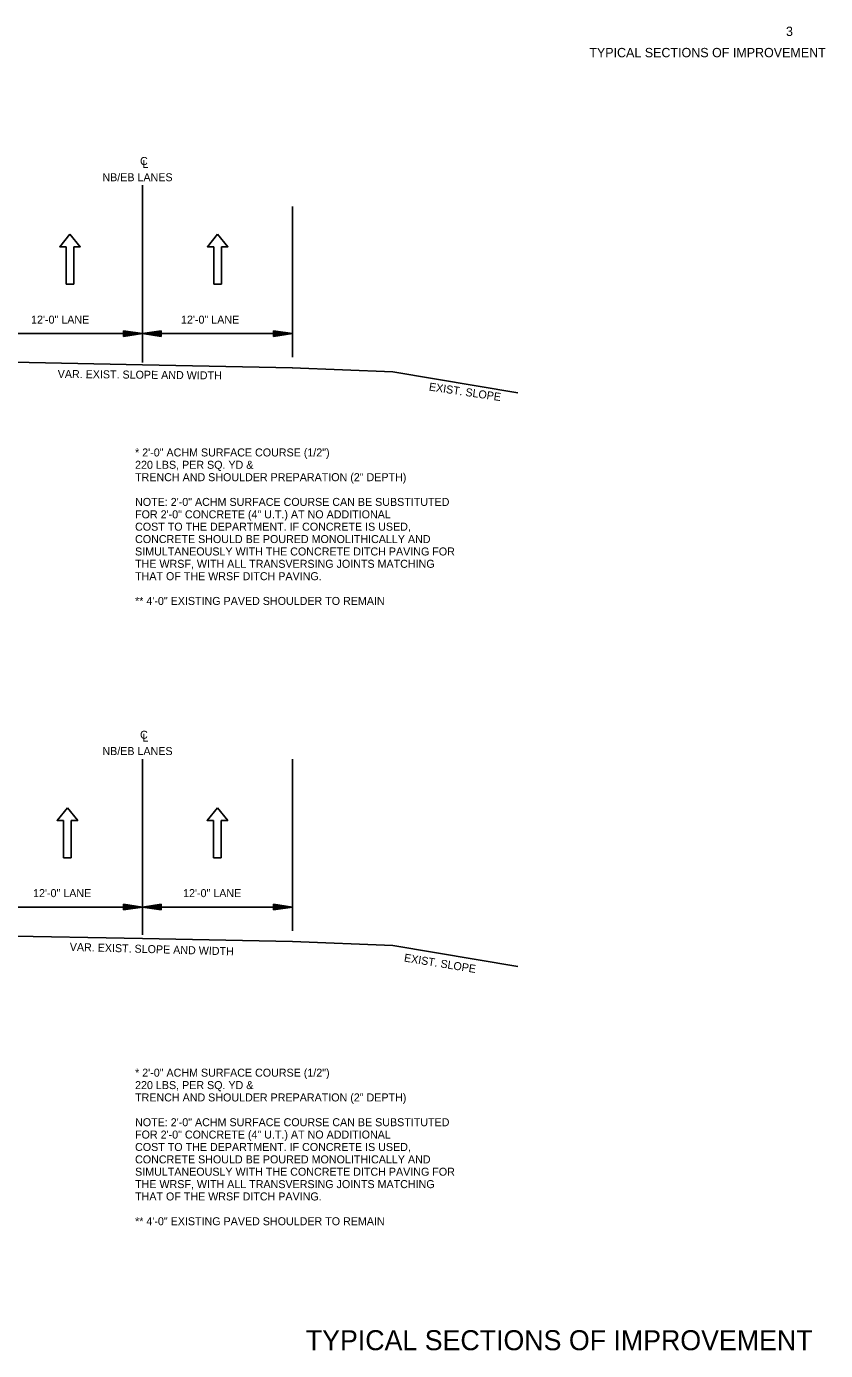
# Model space of a CAD drawing. Extents: x 1641422 to 1649187, y 577497 to 580642.
# Drawn here: x 1646438 to 1647636, y 578610 to 580596 of the extents above; entities that cross this region are included whole.
import ezdxf

# ---------------------------------------------------------------- set-up
doc = ezdxf.new("R2010")
doc.units = 0
doc.layers.add('R_Border', color=7, linetype='Continuous')
doc.layers.add('R_Draft', color=7, linetype='Continuous')

msp = doc.modelspace()

# ---------------------------------------------------------------- linework, layer by layer
at = {"layer": 'R_Draft'}
for p, q in [((1646611.6, 580091.7), (1646611.6, 580357.7)), ((1646836.6, 580100), (1646836.6, 580325.7)), ((1646497.2, 580265.6), (1646497.2, 580209.5)), ((1646508.9, 580265.6), (1646508.9, 580209.5)), ((1646718.7, 580265.6), (1646718.7, 580209.5)), ((1646730.4, 580265.6), (1646730.4, 580209.5)), ((1646497.2, 580209.5), (1646508.9, 580209.5)), ((1646718.7, 580209.5), (1646730.4, 580209.5)), ((1646611.6, 580135.3), (1646386.6, 580135.3)), ((1646583.5, 580139.5), (1646611.6, 580135.3)), ((1646583.5, 580139.5), (1646583.5, 580131.1)), ((1646583.5, 580138.8), (1646607, 580135.3)), ((1646583.5, 580138.1), (1646602.1, 580135.3)), ((1646583.5, 580137.4), (1646597.4, 580135.3)), ((1646583.5, 580136.7), (1646592.7, 580135.3)), ((1646583.5, 580136), (1646588, 580135.3)), ((1646583.5, 580131.1), (1646611.6, 580135.3)), ((1646583.5, 580133.9), (1646592.7, 580135.3)), ((1646583.5, 580132.5), (1646602.1, 580135.3)), ((1646583.5, 580131.8), (1646607, 580135.3)), ((1646583.5, 580133.2), (1646597.4, 580135.3)), ((1646583.5, 580134.6), (1646588, 580135.3)), ((1646639.8, 580139.5), (1646611.6, 580135.3)), ((1646836.6, 580135.3), (1646611.6, 580135.3)), ((1646639.8, 580131.1), (1646611.6, 580135.3)), ((1646639.8, 580138.8), (1646616.3, 580135.3)), ((1646639.8, 580131.8), (1646616.3, 580135.3)), ((1646639.8, 580138.1), (1646621.2, 580135.3)), ((1646639.8, 580132.5), (1646621.2, 580135.3)), ((1646639.8, 580137.4), (1646625.9, 580135.3)), ((1646639.8, 580133.2), (1646625.9, 580135.3)), ((1646639.8, 580136.7), (1646630.6, 580135.3)), ((1646639.8, 580133.9), (1646630.6, 580135.3)), ((1646639.8, 580136), (1646635.3, 580135.3)), ((1646639.8, 580134.6), (1646635.3, 580135.3)), ((1646639.8, 580131.1), (1646639.8, 580139.5)), ((1646808.5, 580139.5), (1646836.6, 580135.3)), ((1646808.5, 580139.5), (1646808.5, 580131.1)), ((1646808.5, 580138.8), (1646831.9, 580135.3)), ((1646808.5, 580138.1), (1646827.1, 580135.3)), ((1646808.5, 580137.4), (1646822.4, 580135.3)), ((1646808.5, 580136.7), (1646817.6, 580135.3)), ((1646808.5, 580136), (1646812.9, 580135.3)), ((1646808.5, 580131.1), (1646836.6, 580135.3)), ((1646808.5, 580133.9), (1646817.6, 580135.3)), ((1646808.5, 580132.5), (1646827.1, 580135.3)), ((1646808.5, 580131.8), (1646831.9, 580135.3)), ((1646808.5, 580133.2), (1646822.4, 580135.3)), ((1646808.5, 580134.6), (1646812.9, 580135.3)), ((1646386.7, 580092.9), (1646611.6, 580088.4)), ((1646611.6, 580088.4), (1646836.6, 580083.9)), ((1646987.1, 580077.8), (1646836.5, 580083.9)), ((1646987.1, 580077.8), (1647174.8, 580046.6)), ((1646611.6, 579233.4), (1646611.6, 579497.2)), ((1646836.6, 579239.8), (1646836.6, 579497.2)), ((1646493.3, 579405.1), (1646493.3, 579349)), ((1646505, 579405.1), (1646505, 579349)), ((1646718.3, 579405.1), (1646718.3, 579349)), ((1646730, 579405.1), (1646730, 579349)), ((1646493.3, 579349), (1646505, 579349)), ((1646718.3, 579349), (1646730, 579349)), ((1646836.6, 579240.2), (1646836.6, 579293.7)), ((1646386.7, 579275.1), (1646611.7, 579275.1)), ((1646583.5, 579279.4), (1646611.6, 579275.1)), ((1646583.5, 579270.9), (1646583.5, 579279.4)), ((1646583.5, 579278.7), (1646607, 579275.1)), ((1646583.5, 579277.9), (1646602.1, 579275.1)), ((1646583.5, 579277.2), (1646597.4, 579275.1)), ((1646583.5, 579276.5), (1646592.7, 579275.1)), ((1646583.5, 579275.8), (1646588, 579275.1)), ((1646583.5, 579270.9), (1646611.6, 579275.1)), ((1646583.5, 579273.8), (1646592.7, 579275.1)), ((1646583.5, 579272.3), (1646602.1, 579275.1)), ((1646583.5, 579271.6), (1646607, 579275.1)), ((1646583.5, 579273), (1646597.4, 579275.1)), ((1646583.5, 579274.5), (1646588, 579275.1)), ((1646639.8, 579279.4), (1646611.6, 579275.1)), ((1646611.6, 579275.1), (1646836.6, 579275.1)), ((1646639.8, 579270.9), (1646611.6, 579275.1)), ((1646639.8, 579278.7), (1646616.3, 579275.1)), ((1646639.8, 579271.6), (1646616.3, 579275.1)), ((1646639.8, 579277.9), (1646621.2, 579275.1)), ((1646639.8, 579272.3), (1646621.2, 579275.1)), ((1646639.8, 579277.2), (1646625.9, 579275.1)), ((1646639.8, 579273), (1646625.9, 579275.1)), ((1646639.8, 579276.5), (1646630.6, 579275.1)), ((1646639.8, 579273.8), (1646630.6, 579275.1)), ((1646639.8, 579275.8), (1646635.3, 579275.1)), ((1646639.8, 579274.5), (1646635.3, 579275.1)), ((1646639.8, 579279.4), (1646639.8, 579270.9)), ((1646808.5, 579279.4), (1646836.6, 579275.1)), ((1646808.5, 579270.9), (1646808.5, 579279.4)), ((1646808.5, 579278.7), (1646832, 579275.1)), ((1646808.5, 579277.9), (1646827.1, 579275.1)), ((1646808.5, 579277.2), (1646822.4, 579275.1)), ((1646808.5, 579276.5), (1646817.7, 579275.1)), ((1646808.5, 579275.8), (1646813, 579275.1)), ((1646808.5, 579270.9), (1646836.6, 579275.1)), ((1646808.5, 579273.8), (1646817.7, 579275.1)), ((1646808.5, 579272.3), (1646827.1, 579275.1)), ((1646808.5, 579271.6), (1646832, 579275.1)), ((1646808.5, 579273), (1646822.4, 579275.1)), ((1646808.5, 579274.5), (1646813, 579275.1)), ((1646386.7, 579232.4), (1646611.7, 579227.9)), ((1646611.6, 579227.9), (1646836.6, 579223.4)), ((1646987.1, 579217.4), (1646836.6, 579223.4)), ((1646987.1, 579217.4), (1647174.8, 579186.1))]:
    msp.add_line(p, q, dxfattribs=at)
for points in [[(1646497.2, 580265.6), (1646487.6, 580265.6), (1646503, 580284.4)], [(1646508.9, 580265.6), (1646518.5, 580265.6), (1646503, 580284.4)], [(1646718.7, 580265.6), (1646709.1, 580265.6), (1646724.5, 580284.4)], [(1646730.4, 580265.6), (1646740, 580265.6), (1646724.5, 580284.4)], [(1646493.3, 579405.1), (1646483.7, 579405.1), (1646499.2, 579423.9)], [(1646505, 579405.1), (1646514.6, 579405.1), (1646499.2, 579423.9)], [(1646718.3, 579405.1), (1646708.7, 579405.1), (1646724.1, 579423.9)], [(1646730, 579405.1), (1646739.6, 579405.1), (1646724.1, 579423.9)]]:
    msp.add_lwpolyline(points, dxfattribs=at)

# ---------------------------------------------------------------- texts
at = {"layer": 'R_Border'}
for s, height, p in [('3', 14, (1647577, 580581.6)), ('TYPICAL SECTIONS OF IMPROVEMENT', 14, (1647282, 580549.7)), ('* 2\'-0" ACHM SURFACE COURSE (1/2")', 12, (1646600.7, 579951)), ('220 LBS, PER SQ. YD &', 12, (1646600.7, 579932.5)), ('TRENCH AND SHOULDER PREPARATION (2" DEPTH)', 12, (1646600.7, 579913.9)), ('NOTE: 2\'-0" ACHM SURFACE COURSE CAN BE SUBSTITUTED', 12, (1646600.7, 579876.8)), ('FOR 2\'-0" CONCRETE (4" U.T.) AT NO ADDITIONAL', 12, (1646600.7, 579858.2)), ('COST TO THE DEPARTMENT. IF CONCRETE IS USED,', 12, (1646600.7, 579839.7)), ('CONCRETE SHOULD BE POURED MONOLITHICALLY AND ', 12, (1646600.7, 579821.1)), ('SIMULTANEOUSLY WITH THE CONCRETE DITCH PAVING FOR', 12, (1646600.7, 579802.5)), ('THE WRSF, WITH ALL TRANSVERSING JOINTS MATCHING', 12, (1646600.7, 579784)), ('THAT OF THE WRSF DITCH PAVING. ', 12, (1646600.7, 579765.4)), ('** 4\'-0" EXISTING PAVED SHOULDER TO REMAIN', 12, (1646600.7, 579728.3)), ('* 2\'-0" ACHM SURFACE COURSE (1/2")', 12, (1646600.7, 579020.8)), ('TRENCH AND SHOULDER PREPARATION (2" DEPTH)', 12, (1646600.7, 578983.7)), ('220 LBS, PER SQ. YD &', 12, (1646600.7, 579002.2)), ('NOTE: 2\'-0" ACHM SURFACE COURSE CAN BE SUBSTITUTED', 12, (1646600.7, 578946.5)), ('FOR 2\'-0" CONCRETE (4" U.T.) AT NO ADDITIONAL', 12, (1646600.7, 578928)), ('COST TO THE DEPARTMENT. IF CONCRETE IS USED,', 12, (1646600.7, 578909.4)), ('CONCRETE SHOULD BE POURED MONOLITHICALLY AND ', 12, (1646600.7, 578890.8)), ('SIMULTANEOUSLY WITH THE CONCRETE DITCH PAVING FOR', 12, (1646600.7, 578872.3)), ('THE WRSF, WITH ALL TRANSVERSING JOINTS MATCHING', 12, (1646600.7, 578853.7)), ('THAT OF THE WRSF DITCH PAVING. ', 12, (1646600.7, 578835.2)), ('** 4\'-0" EXISTING PAVED SHOULDER TO REMAIN', 12, (1646600.7, 578798)), ('TYPICAL SECTIONS OF IMPROVEMENT', 30, (1646856.8, 578610.6))]:
    msp.add_text(s, height=height, dxfattribs=at).set_placement(p)
at = {"layer": 'R_Draft'}
for s, p in [('C', (1646608.2, 580388.1)), ('L', (1646611.7, 580383.7)), ('NB/EB LANES', (1646551.7, 580363.7)), ('12\'-0" LANE', (1646444.7, 580150.2)), ('12\'-0" LANE', (1646669.6, 580150.2)), ('C', (1646608.2, 579527.6)), ('L', (1646611.7, 579523.2)), ('NB/EB LANES', (1646551.7, 579503.2)), ('12\'-0" LANE', (1646447.7, 579290.1)), ('12\'-0" LANE', (1646672.7, 579290.1))]:
    msp.add_text(s, height=12, dxfattribs=at).set_placement(p)
for s, rotation, p in [('VAR. EXIST. SLOPE AND WIDTH', 359.4463, (1646484.6, 580068.8)), ('EXIST. SLOPE', 351.5755, (1647040.9, 580050)), ('VAR. EXIST. SLOPE AND WIDTH', 358.3904, (1646502.6, 579209.6)), ('EXIST. SLOPE', 350.8466, (1647003.5, 579193.6))]:
    msp.add_text(s, height=12, rotation=rotation, dxfattribs=at).set_placement(p)

doc.saveas('drawing.dxf')
